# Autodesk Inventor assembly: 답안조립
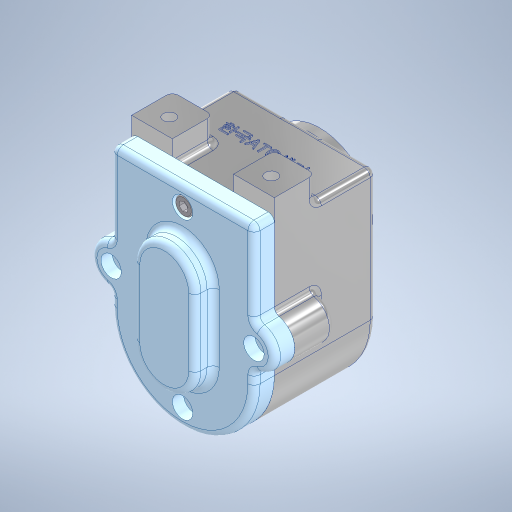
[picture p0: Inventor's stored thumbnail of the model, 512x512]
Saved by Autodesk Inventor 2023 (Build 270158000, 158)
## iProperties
Created: 2024-03
Part Number: 답안조립
Document SubType Name: Assembly
Designer: asung
Author: asung
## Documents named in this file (8)
- C:\Users\asung\Desktop\답안조립.iam
- C:\Users\asung\Desktop\740304V1005\본체.0007.ipt
- C:\Users\asung\Desktop\740304V1005\오일레스 부시.ipt
- C:\Users\asung\Desktop\740304V1005\커버.ipt
- C:\Users\asung\Desktop\740304V1005\오일 실 14 25 7.ipt
- C:\Users\asung\Desktop\740304V1005\구동기어.ipt
- C:\Users\asung\Desktop\740304V1005\스퍼기어.ipt
- C:\Users\asung\Desktop\740304V1005\육각 소켓 머리 볼트 M5x12.ipt
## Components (1 placed, 1 different names)
1. 구동기어:1
